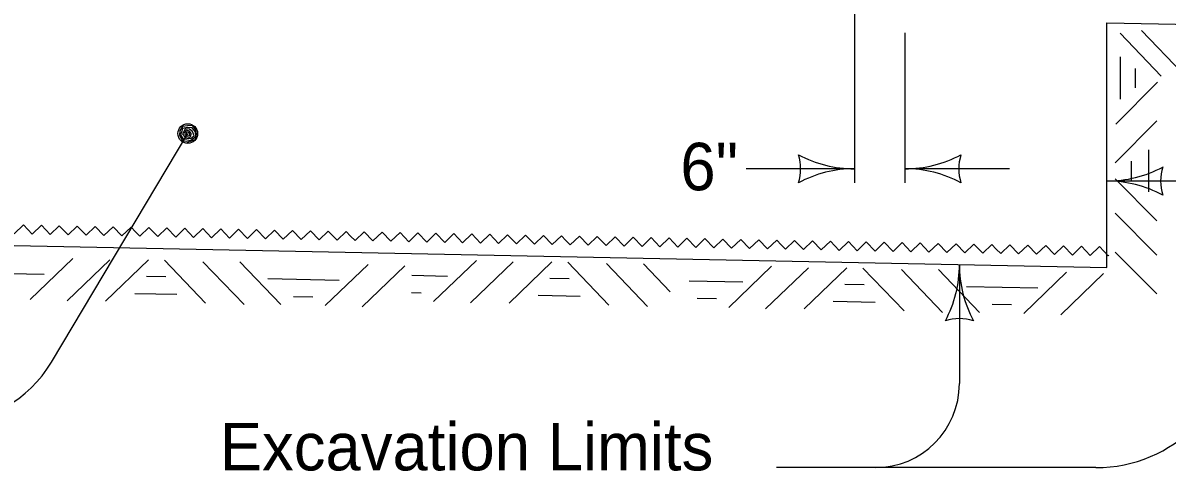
# Model space of a CAD drawing. Extents: x -2134934 to -2124557, y -2139046 to -2134021.
# Drawn here: x -2127032.7 to -2126646.7, y -2137450.5 to -2137299.6 of the extents above; entities that cross this region are included whole.
import ezdxf

# ---------------------------------------------------------------- set-up
doc = ezdxf.new("R2010")
doc.units = 0
doc.layers.add('BridgeSuperStructureExisting', color=7, linetype='Continuous')
doc.layers.add('dsnStdLabel', color=7, linetype='Continuous')

msp = doc.modelspace()

# ---------------------------------------------------------------- linework, layer by layer
at = {"layer": 'BridgeSuperStructureExisting'}
for p, q in [((-2126752.19, -2137292.66), (-2126752.19, -2137353.4)), ((-2126667.12, -2137381.97), (-2126667.12, -2137299.55)), ((-2126667.12, -2137299.55), (-2126489.26, -2137303.12)), ((-2126735.17, -2137302.91), (-2126735.17, -2137353.4)), ((-2126662.62, -2137303.03), (-2126648.76, -2137317.45)), ((-2126655.4, -2137302.1), (-2126641.54, -2137316.52)), ((-2126664.08, -2137333.65), (-2126649.94, -2137319.51)), ((-2126664.31, -2137346.66), (-2126650.17, -2137332.52)), ((-2127023.06, -2137413.8), (-2126977.04, -2137336.83)), ((-2126752.19, -2137348.68), (-2126788.72, -2137348.68)), ((-2126699.95, -2137348.68), (-2126735.17, -2137348.68)), ((-2126642.39, -2137352.8), (-2126667.12, -2137352.8)), ((-2126664.31, -2137352.07), (-2126650.17, -2137366.21)), ((-2127483.71, -2137365.58), (-2126667.12, -2137381.97)), ((-2126664.31, -2137363.65), (-2126650.17, -2137377.79)), ((-2126664.31, -2137376.71), (-2126650.17, -2137390.85)), ((-2127015.78, -2137378.88), (-2127030.21, -2137392.74)), ((-2127003.34, -2137379.36), (-2127017.76, -2137393.21)), ((-2126990.33, -2137379.39), (-2127004.75, -2137393.25)), ((-2126984.92, -2137379.5), (-2126971.06, -2137393.92)), ((-2126971.92, -2137379.99), (-2126958.06, -2137394.41)), ((-2126959.47, -2137380.01), (-2126945.61, -2137394.43)), ((-2126916.25, -2137380.88), (-2126930.67, -2137394.73)), ((-2126879.71, -2137379.52), (-2126894.14, -2137393.37)), ((-2126867.27, -2137380), (-2126881.69, -2137393.85)), ((-2126854.26, -2137380.03), (-2126868.68, -2137393.89)), ((-2126848.85, -2137380.14), (-2126834.99, -2137394.56)), ((-2126835.85, -2137380.63), (-2126821.99, -2137395.05)), ((-2126823.4, -2137380.65), (-2126814.3, -2137390.12)), ((-2126716.8, -2137380.97), (-2126716.8, -2137420.98)), ((-2126903.81, -2137381.35), (-2126918.23, -2137395.21)), ((-2126780.18, -2137381.52), (-2126794.61, -2137395.37)), ((-2126767.74, -2137381.99), (-2126782.16, -2137395.85)), ((-2126754.73, -2137382.03), (-2126769.15, -2137395.88)), ((-2126749.32, -2137382.14), (-2126735.46, -2137396.56)), ((-2126736.32, -2137382.62), (-2126722.46, -2137397.05)), ((-2126723.87, -2137382.65), (-2126710.01, -2137397.07)), ((-2126680.65, -2137383.51), (-2126695.07, -2137397.37)), ((-2126668.21, -2137383.99), (-2126682.63, -2137397.85)), ((-2126670.75, -2137449.33), (-2126778.52, -2137449.33))]:
    msp.add_line(p, q, dxfattribs=at)
for points in [[(-2126662.5, -2137325.22), (-2126662.5, -2137311.02)], [(-2126657.41, -2137321.39), (-2126657.41, -2137314.85)], [(-2126977.29, -2137339.87), (-2126976.18, -2137339.37), (-2126974.45, -2137338.83), (-2126974.11, -2137337.07), (-2126974.35, -2137335.52), (-2126975.46, -2137334.09), (-2126977.11, -2137334.24), (-2126978.85, -2137334.48), (-2126979.69, -2137335.87), (-2126979.84, -2137337.33), (-2126978.81, -2137339.25), (-2126977.54, -2137339.41), (-2126975.8, -2137338.97), (-2126974.37, -2137337.86), (-2126974.42, -2137336.2), (-2126975.53, -2137334.88), (-2126977.09, -2137334.73), (-2126978.83, -2137335.07), (-2126979.1, -2137336.05), (-2126979.45, -2137337.22), (-2126978.64, -2137338.66), (-2126977.37, -2137338.63), (-2126975.92, -2137338.39), (-2126974.87, -2137337.58), (-2126975.4, -2137336.13), (-2126976.49, -2137335.29), (-2126977.96, -2137335.23), (-2126978.32, -2137336.03), (-2126978.78, -2137336.91), (-2126978.07, -2137338.06), (-2126976.99, -2137338.32), (-2126976.03, -2137337.81), (-2126975.96, -2137336.74), (-2126976.47, -2137335.97), (-2126977.46, -2137335.7), (-2126977.93, -2137336.11), (-2126978.2, -2137336.7), (-2126977.69, -2137337.56), (-2126977.01, -2137337.74), (-2126976.34, -2137337.33), (-2126976.45, -2137336.75), (-2126976.95, -2137336.37), (-2126977.63, -2137336.39), (-2126977.61, -2137336.88), (-2126977.02, -2137337.15)], [(-2126652.95, -2137356.46), (-2126652.95, -2137342.27)], [(-2126658.81, -2137352.63), (-2126658.81, -2137346.1)], [(-2127035.56, -2137370.56), (-2127032.48, -2137367.6), (-2127029.51, -2137370.69), (-2127026.43, -2137367.72), (-2127023.46, -2137370.8), (-2127020.38, -2137367.84), (-2127017.42, -2137370.92), (-2127014.33, -2137367.96), (-2127011.37, -2137371.05), (-2127008.28, -2137368.09), (-2127005.32, -2137371.17), (-2127002.23, -2137368.21), (-2126999.27, -2137371.29), (-2126996.18, -2137368.32), (-2126994.7, -2137369.87)], [(-2126994.7, -2137369.87), (-2126993.22, -2137371.41), (-2126990.14, -2137368.45), (-2126987.17, -2137371.53), (-2126984.09, -2137368.57), (-2126981.12, -2137371.66), (-2126978.04, -2137368.69), (-2126975.07, -2137371.78), (-2126971.99, -2137368.81), (-2126969.02, -2137371.9), (-2126965.94, -2137368.93), (-2126962.98, -2137372.02), (-2126959.89, -2137369.06), (-2126956.93, -2137372.14), (-2126953.84, -2137369.18), (-2126950.88, -2137372.26), (-2126947.79, -2137369.3), (-2126944.83, -2137372.38), (-2126941.75, -2137369.42), (-2126938.78, -2137372.5), (-2126935.7, -2137369.54), (-2126932.73, -2137372.63), (-2126929.65, -2137369.66), (-2126926.68, -2137372.75), (-2126923.6, -2137369.78), (-2126922.12, -2137371.33)], [(-2126922.12, -2137371.33), (-2126920.64, -2137372.87), (-2126917.55, -2137369.9), (-2126914.59, -2137372.99), (-2126911.5, -2137370.03), (-2126908.54, -2137373.11), (-2126905.45, -2137370.15), (-2126902.49, -2137373.23), (-2126899.4, -2137370.27), (-2126896.44, -2137373.35), (-2126893.35, -2137370.39), (-2126890.39, -2137373.48), (-2126887.31, -2137370.51), (-2126884.34, -2137373.6), (-2126881.26, -2137370.63), (-2126878.29, -2137373.72), (-2126875.21, -2137370.75), (-2126872.24, -2137373.84), (-2126869.16, -2137370.88), (-2126866.2, -2137373.96), (-2126863.11, -2137371), (-2126860.15, -2137374.08), (-2126857.06, -2137371.12), (-2126854.1, -2137374.2), (-2126851.01, -2137371.24), (-2126849.54, -2137372.78)], [(-2126849.54, -2137372.78), (-2126848.05, -2137374.32), (-2126844.96, -2137371.36), (-2126842, -2137374.45), (-2126838.92, -2137371.48), (-2126835.95, -2137374.57), (-2126832.87, -2137371.6), (-2126829.9, -2137374.69), (-2126826.82, -2137371.72), (-2126823.85, -2137374.81), (-2126820.77, -2137371.85), (-2126817.81, -2137374.93), (-2126814.72, -2137371.97), (-2126811.76, -2137375.06), (-2126808.68, -2137372.09), (-2126805.71, -2137375.17), (-2126802.63, -2137372.21), (-2126799.66, -2137375.29), (-2126796.58, -2137372.33), (-2126793.61, -2137375.42), (-2126790.53, -2137372.46), (-2126787.57, -2137375.54), (-2126784.48, -2137372.58), (-2126781.52, -2137375.66), (-2126778.43, -2137372.69), (-2126776.95, -2137374.24)], [(-2126776.95, -2137374.24), (-2126775.47, -2137375.78), (-2126772.38, -2137372.82), (-2126769.42, -2137375.9), (-2126766.33, -2137372.94), (-2126763.37, -2137376.03), (-2126760.29, -2137373.06), (-2126757.32, -2137376.15), (-2126754.24, -2137373.18), (-2126751.27, -2137376.26), (-2126748.19, -2137373.3), (-2126745.22, -2137376.39), (-2126742.13, -2137373.43), (-2126739.17, -2137376.51), (-2126736.09, -2137373.55), (-2126733.13, -2137376.63), (-2126730.04, -2137373.67), (-2126727.08, -2137376.75), (-2126723.99, -2137373.79), (-2126721.03, -2137376.87), (-2126717.94, -2137373.91), (-2126714.98, -2137377), (-2126711.9, -2137374.03), (-2126708.93, -2137377.12), (-2126705.85, -2137374.15), (-2126704.36, -2137375.7)], [(-2126704.36, -2137375.7), (-2126702.88, -2137377.24), (-2126699.8, -2137374.27), (-2126696.83, -2137377.36), (-2126693.75, -2137374.4), (-2126690.79, -2137377.48), (-2126687.7, -2137374.52), (-2126684.74, -2137377.6), (-2126681.65, -2137374.64), (-2126678.69, -2137377.72), (-2126675.6, -2137374.76), (-2126672.64, -2137377.85), (-2126669.55, -2137374.88), (-2126666.59, -2137377.97), (-2126666.37, -2137377.78)], [(-2127043.53, -2137383.8), (-2127025.47, -2137384.16)], [(-2126991, -2137384.88), (-2126984.47, -2137385.01)], [(-2126901.43, -2137384.56), (-2126889.4, -2137384.8)], [(-2126950, -2137385.68), (-2126925.94, -2137386.16)], [(-2126854.93, -2137385.52), (-2126848.4, -2137385.65)], [(-2126807.93, -2137386.44), (-2126789.87, -2137386.8)], [(-2126755.4, -2137387.51), (-2126748.87, -2137387.64)], [(-2126714.4, -2137388.31), (-2126690.34, -2137388.8)], [(-2126994.95, -2137390.65), (-2126980.76, -2137390.94)], [(-2126941.35, -2137391.65), (-2126934.82, -2137391.78)], [(-2126901.55, -2137390.36), (-2126898.28, -2137390.42)], [(-2126858.88, -2137391.29), (-2126844.69, -2137391.58)], [(-2126805.28, -2137392.29), (-2126798.75, -2137392.42)], [(-2126759.35, -2137393.29), (-2126745.16, -2137393.58)], [(-2126705.75, -2137394.29), (-2126699.22, -2137394.42)]]:
    msp.add_lwpolyline(points, dxfattribs=at)
msp.add_circle((-2126977.04, -2137336.83), 3.31, dxfattribs=at)
for centre, radius, start, end in [((-2126785.87, -2137348.68), 15.52, 342.2666, 17.7334), ((-2126752.18, -2137308.5), 40.18, 241.9275, 270), ((-2126735.17, -2137308.5), 40.18, 270, 298.0725), ((-2126701.49, -2137348.68), 15.52, 162.2666, 197.7334), ((-2126752.18, -2137388.85), 40.18, 90, 118.0725), ((-2126735.17, -2137388.85), 40.18, 61.9275, 90), ((-2126667.11, -2137312.63), 40.18, 270, 298.0725), ((-2126633.42, -2137352.8), 15.52, 162.2666, 197.7334), ((-2126667.11, -2137392.98), 40.18, 61.9275, 90), ((-2126756.97, -2137380.97), 40.18, 331.9275, 360), ((-2126676.62, -2137380.97), 40.18, 180, 208.0725), ((-2126716.8, -2137414.66), 15.52, 72.2666, 107.7334), ((-2126670.75, -2137402.07), 47.27, 270, 360), ((-2127059.56, -2137391.97), 42.54, 270, 329.1249), ((-2126745.15, -2137420.98), 28.36, 270, 360)]:
    msp.add_arc(centre, radius, start, end, dxfattribs=at)

# ---------------------------------------------------------------- texts
at = {"layer": 'dsnStdLabel'}
for s, p in [('6"', (-2126810.91, -2137355.93)), ('Excavation Limits', (-2126966.27, -2137450.27))]:
    msp.add_text(s, height=16, dxfattribs=at).set_placement(p)

doc.saveas('drawing.dxf')
